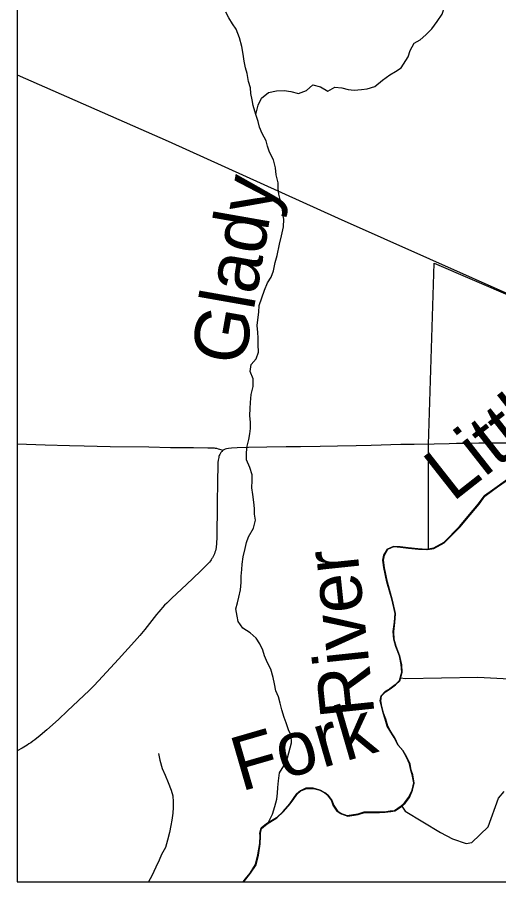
# Model space of a CAD drawing. Extents: x 0 to 1052, y -194 to 246.
# Drawn here: x 1.982 to 2.825, y 14.205 to 15.72 of the extents above; entities that cross this region are included whole.
import ezdxf

# ---------------------------------------------------------------- set-up
doc = ezdxf.new("R2010")
doc.units = 0
for name, color, linetype in [('GM_X_Corporation', 7, 'Continuous'), ('GM_X_County_Road', 7, 'Continuous'), ('GM_X_Major_River', 7, 'Continuous'), ('GM_X_Major_River_Text', 7, 'Continuous'), ('GM_X_Minor_River', 7, 'Continuous'), ('GM_X_Minor_River_Text', 7, 'Continuous'), ('GM_X_Rail_Line', 7, 'Continuous')]:
    doc.layers.add(name, color=color, linetype=linetype)

msp = doc.modelspace()

# ---------------------------------------------------------------- linework, layer by layer
at = {"layer": 'GM_X_Corporation'}
for points in [[(1.9822, 21.0055), (1.9822, 14.2055), (2.3779, 14.2055), (2.3814, 14.2102), (2.39, 14.2207), (2.3994, 14.2357), (2.4035, 14.2523), (2.4066, 14.2724), (2.4072, 14.2857), (2.4069, 14.2907), (2.409, 14.299), (2.4186, 14.3071), (2.4359, 14.3174), (2.4476, 14.3286), (2.4592, 14.3421), (2.4658, 14.3511), (2.4709, 14.3586), (2.4779, 14.3649), (2.4875, 14.3692), (2.5, 14.3694), (2.5121, 14.3661), (2.5207, 14.361), (2.526, 14.3571), (2.5323, 14.3482), (2.5355, 14.3394), (2.5425, 14.329), (2.5489, 14.3247), (2.5599, 14.3207), (2.5782, 14.3238), (2.5892, 14.327), (2.6029, 14.3271), (2.6158, 14.3272), (2.6253, 14.3274), (2.6352, 14.3288), (2.6425, 14.3298), (2.6525, 14.3364), (2.6602, 14.3435), (2.668, 14.3536), (2.6736, 14.366), (2.6765, 14.3785), (2.6737, 14.393), (2.6712, 14.401), (2.6691, 14.4117), (2.6637, 14.4239), (2.6571, 14.4351), (2.6485, 14.4451), (2.6423, 14.4578), (2.636, 14.4674), (2.6301, 14.4782), (2.6266, 14.4904), (2.6226, 14.5011), (2.6198, 14.513), (2.6177, 14.5225), (2.6194, 14.5312), (2.6264, 14.5387), (2.6344, 14.5434), (2.6437, 14.5505), (2.6514, 14.5579), (2.6555, 14.5727), (2.6546, 14.586), (2.6515, 14.6009), (2.645, 14.6177), (2.6414, 14.6303), (2.6406, 14.644), (2.6424, 14.6599), (2.6438, 14.6751), (2.6386, 14.6984), (2.6293, 14.7305), (2.6241, 14.7557), (2.6225, 14.769), (2.6242, 14.7777), (2.6304, 14.7882), (2.6408, 14.7929), (2.6525, 14.792), (2.6666, 14.7902), (2.6836, 14.7883), (2.6996, 14.7876), (2.711, 14.7897), (2.7291, 14.7996), (2.7566, 14.8275), (2.7741, 14.8485), (2.79, 14.8672), (2.7998, 14.881), (2.8225, 14.8973), (2.8433, 14.9121)], [(1.9822, 21.0055), (1.9822, 14.2055), (2.3779, 14.2055), (2.3814, 14.2102), (2.39, 14.2207), (2.3994, 14.2357), (2.4035, 14.2523), (2.4066, 14.2724), (2.4072, 14.2857), (2.4069, 14.2907), (2.409, 14.299), (2.4186, 14.3071), (2.4359, 14.3174), (2.4476, 14.3286), (2.4592, 14.3421), (2.4658, 14.3511), (2.4709, 14.3586), (2.4779, 14.3649), (2.4875, 14.3692), (2.5, 14.3694), (2.5121, 14.3661), (2.5207, 14.361), (2.526, 14.3571), (2.5323, 14.3482), (2.5355, 14.3394), (2.5425, 14.329), (2.5489, 14.3247), (2.5599, 14.3207), (2.5782, 14.3238), (2.5892, 14.327), (2.6029, 14.3271), (2.6158, 14.3272), (2.6253, 14.3274), (2.6352, 14.3288), (2.6425, 14.3298), (2.6525, 14.3364), (2.6602, 14.3435), (2.668, 14.3536), (2.6736, 14.366), (2.6765, 14.3785), (2.6737, 14.393), (2.6712, 14.401), (2.6691, 14.4117), (2.6637, 14.4239), (2.6571, 14.4351), (2.6485, 14.4451), (2.6423, 14.4578), (2.636, 14.4674), (2.6301, 14.4782), (2.6266, 14.4904), (2.6226, 14.5011), (2.6198, 14.513), (2.6177, 14.5225), (2.6194, 14.5312), (2.6264, 14.5387), (2.6344, 14.5434), (2.6437, 14.5505), (2.6514, 14.5579), (2.6555, 14.5727), (2.6546, 14.586), (2.6515, 14.6009), (2.645, 14.6177), (2.6414, 14.6303), (2.6406, 14.644), (2.6424, 14.6599), (2.6438, 14.6751), (2.6386, 14.6984), (2.6293, 14.7305), (2.6241, 14.7557), (2.6225, 14.769), (2.6242, 14.7777), (2.6304, 14.7882), (2.6408, 14.7929), (2.6525, 14.792), (2.6666, 14.7902), (2.6836, 14.7883), (2.6996, 14.7876), (2.711, 14.7897), (2.7291, 14.7996), (2.7566, 14.8275), (2.7741, 14.8485), (2.79, 14.8672), (2.7998, 14.881), (2.8225, 14.8973), (2.8433, 14.9121)], [(2.8341, 14.9056), (2.8001, 14.8813), (2.7871, 14.8635), (2.7571, 14.8282), (2.7291, 14.7996), (2.7108, 14.7896), (2.7022, 14.7881), (2.7023, 14.9715), (2.712, 15.289), (2.9863, 15.171)], [(2.8433, 14.9121), (2.8225, 14.8973), (2.7998, 14.881), (2.79, 14.8672), (2.7741, 14.8485), (2.7566, 14.8275), (2.7291, 14.7996), (2.711, 14.7897), (2.6996, 14.7876), (2.6836, 14.7883), (2.6666, 14.7902), (2.6525, 14.792), (2.6408, 14.7929), (2.6304, 14.7882), (2.6242, 14.7777), (2.6225, 14.769), (2.6241, 14.7557), (2.6293, 14.7305), (2.6386, 14.6984), (2.6438, 14.6751), (2.6424, 14.6599), (2.6406, 14.644), (2.6414, 14.6303), (2.645, 14.6177), (2.6515, 14.6009), (2.6546, 14.586), (2.6555, 14.5727), (2.6514, 14.5579), (2.6437, 14.5505), (2.6344, 14.5434), (2.6264, 14.5387), (2.6194, 14.5312), (2.6177, 14.5225), (2.6198, 14.513), (2.6226, 14.5011), (2.6266, 14.4904), (2.6301, 14.4782), (2.636, 14.4674), (2.6423, 14.4578), (2.6485, 14.4451), (2.6571, 14.4351), (2.6637, 14.4239), (2.6691, 14.4117), (2.6712, 14.401), (2.6737, 14.393), (2.6765, 14.3785), (2.6736, 14.366), (2.668, 14.3536), (2.6602, 14.3435), (2.6525, 14.3364), (2.6425, 14.3298), (2.6352, 14.3288), (2.6253, 14.3274), (2.6158, 14.3272), (2.6029, 14.3271), (2.5892, 14.327), (2.5782, 14.3238), (2.5599, 14.3207), (2.5489, 14.3247), (2.5425, 14.329), (2.5355, 14.3394), (2.5323, 14.3482), (2.526, 14.3571), (2.5207, 14.361), (2.5121, 14.3661), (2.5, 14.3694), (2.4875, 14.3692), (2.4779, 14.3649), (2.4709, 14.3586), (2.4658, 14.3511), (2.4592, 14.3421), (2.4476, 14.3286), (2.4359, 14.3174), (2.4186, 14.3071), (2.409, 14.299), (2.4069, 14.2907), (2.4072, 14.2857), (2.4066, 14.2724), (2.4035, 14.2523), (2.3994, 14.2357), (2.39, 14.2207), (2.3814, 14.2102), (2.3779, 14.2055), (8.7822, 14.2055)], [(2.8433, 14.9121), (2.8225, 14.8973), (2.7998, 14.881), (2.79, 14.8672), (2.7741, 14.8485), (2.7566, 14.8275), (2.7291, 14.7996), (2.711, 14.7897), (2.6996, 14.7876), (2.6836, 14.7883), (2.6666, 14.7902), (2.6525, 14.792), (2.6408, 14.7929), (2.6304, 14.7882), (2.6242, 14.7777), (2.6225, 14.769), (2.6241, 14.7557), (2.6293, 14.7305), (2.6386, 14.6984), (2.6438, 14.6751), (2.6424, 14.6599), (2.6406, 14.644), (2.6414, 14.6303), (2.645, 14.6177), (2.6515, 14.6009), (2.6546, 14.586), (2.6555, 14.5727), (2.6514, 14.5579), (2.6437, 14.5505), (2.6344, 14.5434), (2.6264, 14.5387), (2.6194, 14.5312), (2.6177, 14.5225), (2.6198, 14.513), (2.6226, 14.5011), (2.6266, 14.4904), (2.6301, 14.4782), (2.636, 14.4674), (2.6423, 14.4578), (2.6485, 14.4451), (2.6571, 14.4351), (2.6637, 14.4239), (2.6691, 14.4117), (2.6712, 14.401), (2.6737, 14.393), (2.6765, 14.3785), (2.6736, 14.366), (2.668, 14.3536), (2.6602, 14.3435), (2.6525, 14.3364), (2.6425, 14.3298), (2.6352, 14.3288), (2.6253, 14.3274), (2.6158, 14.3272), (2.6029, 14.3271), (2.5892, 14.327), (2.5782, 14.3238), (2.5599, 14.3207), (2.5489, 14.3247), (2.5425, 14.329), (2.5355, 14.3394), (2.5323, 14.3482), (2.526, 14.3571), (2.5207, 14.361), (2.5121, 14.3661), (2.5, 14.3694), (2.4875, 14.3692), (2.4779, 14.3649), (2.4709, 14.3586), (2.4658, 14.3511), (2.4592, 14.3421), (2.4476, 14.3286), (2.4359, 14.3174), (2.4186, 14.3071), (2.409, 14.299), (2.4069, 14.2907), (2.4072, 14.2857), (2.4066, 14.2724), (2.4035, 14.2523), (2.3994, 14.2357), (2.39, 14.2207), (2.3814, 14.2102), (2.3779, 14.2055), (5.0927, 14.2055)]]:
    msp.add_lwpolyline(points, dxfattribs=at)
at = {"layer": 'GM_X_County_Road'}
for points in [[(1.9822, 14.9723), (2.0308, 14.971), (2.0736, 14.9698), (2.0991, 14.9691), (2.145, 14.9681), (2.2127, 14.967), (2.2506, 14.9663), (2.2798, 14.9663), (2.291, 14.9661), (2.3158, 14.9656), (2.3205, 14.9655), (2.3251, 14.9654), (2.3269, 14.9653), (2.3289, 14.9651), (2.3311, 14.9648), (2.3342, 14.9639), (2.3427, 14.9613)], [(2.3427, 14.9613), (2.3417, 14.9607), (2.3401, 14.9592), (2.3387, 14.9573), (2.3373, 14.955), (2.3366, 14.9537), (2.3359, 14.9521), (2.3353, 14.9502), (2.3348, 14.9484), (2.3344, 14.9462), (2.334, 14.944), (2.3336, 14.9396), (2.3325, 14.9017), (2.3323, 14.8725), (2.3319, 14.8489), (2.3318, 14.8259), (2.3313, 14.8048), (2.3311, 14.8019), (2.331, 14.7992), (2.3308, 14.7962), (2.3305, 14.7931), (2.3302, 14.7907), (2.3297, 14.7882), (2.3291, 14.7853), (2.3283, 14.7827), (2.3275, 14.78), (2.3264, 14.7775), (2.3253, 14.775), (2.3241, 14.773), (2.3231, 14.7714), (2.3218, 14.7694), (2.3203, 14.7674), (2.3188, 14.7655), (2.3172, 14.7636), (2.3147, 14.7609), (2.3125, 14.7587), (2.3024, 14.7486), (2.2784, 14.7261), (2.2528, 14.702), (2.2476, 14.6971), (2.244, 14.6935), (2.2401, 14.6897), (2.2365, 14.6858), (2.2333, 14.6823), (2.2301, 14.6785), (2.2257, 14.6733), (2.2053, 14.6474), (2.1967, 14.6368), (2.1874, 14.626), (2.1595, 14.5952), (2.1245, 14.5573), (2.1159, 14.5484), (2.108, 14.5405), (2.0701, 14.5046), (2.0541, 14.4899), (2.0338, 14.4716), (2.0221, 14.4614), (2.0129, 14.4541), (2.0094, 14.4515), (2.0059, 14.449), (2.0024, 14.4467), (1.9992, 14.4446), (1.9907, 14.4396), (1.9822, 14.435)], [(2.7122, 14.972), (2.6774, 14.9716), (2.6537, 14.9712), (2.6016, 14.9695), (2.5755, 14.969), (2.5426, 14.9682), (2.5128, 14.9677), (2.4781, 14.9675), (2.4527, 14.9674), (2.4192, 14.9669), (2.3869, 14.9662), (2.367, 14.9656), (2.357, 14.9649), (2.3519, 14.9644), (2.3486, 14.9638), (2.346, 14.9631), (2.3439, 14.9621), (2.3427, 14.9613)], [(2.8378, 14.9737), (2.8204, 14.9736), (2.8011, 14.9737), (2.7905, 14.9735), (2.7675, 14.9731), (2.7514, 14.9729), (2.7383, 14.9726), (2.7122, 14.972)]]:
    msp.add_lwpolyline(points, dxfattribs=at)
at = {"layer": 'GM_X_Major_River'}
for points in [[(2.6611, 14.3431), (2.6689, 14.3532), (2.6744, 14.3656), (2.6773, 14.3781), (2.6746, 14.3926), (2.672, 14.4006), (2.67, 14.4113), (2.6645, 14.4236), (2.6579, 14.4347), (2.6493, 14.4448), (2.6431, 14.4574), (2.6369, 14.467), (2.631, 14.4778), (2.6274, 14.49), (2.6234, 14.5008), (2.6206, 14.5126), (2.6185, 14.5221), (2.6202, 14.5308), (2.6272, 14.5383), (2.6353, 14.5431), (2.6445, 14.5501), (2.6523, 14.5576), (2.6564, 14.5723), (2.6555, 14.5856), (2.6523, 14.6005), (2.6458, 14.6174), (2.6423, 14.63), (2.6414, 14.6437), (2.6432, 14.6596), (2.6447, 14.6747), (2.6394, 14.698), (2.6302, 14.7301), (2.6249, 14.7553), (2.6233, 14.7686), (2.625, 14.7773), (2.6313, 14.7879), (2.6416, 14.7926), (2.6534, 14.7916), (2.6674, 14.7898), (2.6845, 14.788), (2.7004, 14.7873), (2.7118, 14.7893), (2.7299, 14.7992), (2.7574, 14.8272), (2.7749, 14.8481), (2.7908, 14.8668), (2.8006, 14.8807), (2.8233, 14.897), (2.8441, 14.9117)], [(2.6611, 14.3431), (2.6689, 14.3532), (2.6744, 14.3656), (2.6773, 14.3781), (2.6746, 14.3926), (2.672, 14.4006), (2.67, 14.4113), (2.6645, 14.4236), (2.6579, 14.4347), (2.6493, 14.4448), (2.6431, 14.4574), (2.6369, 14.4671), (2.631, 14.4778), (2.6274, 14.49), (2.6234, 14.5008), (2.6206, 14.5126), (2.6185, 14.5221), (2.6202, 14.5308), (2.6272, 14.5383), (2.6353, 14.5431), (2.6445, 14.5501), (2.6523, 14.5576), (2.6564, 14.5723), (2.6555, 14.5856), (2.6523, 14.6005), (2.6458, 14.6174), (2.6423, 14.63), (2.6414, 14.6437), (2.6432, 14.6596), (2.6447, 14.6747), (2.6394, 14.698), (2.6302, 14.7301), (2.6249, 14.7553), (2.6233, 14.7686), (2.625, 14.7773), (2.6313, 14.7879), (2.6416, 14.7926), (2.6534, 14.7916), (2.6674, 14.7898), (2.6845, 14.788), (2.7004, 14.7873), (2.7118, 14.7893), (2.7299, 14.7992), (2.7574, 14.8272), (2.7749, 14.8481), (2.7908, 14.8668), (2.8006, 14.8807), (2.8233, 14.897), (2.8441, 14.9117)], [(2.379, 14.2055), (2.3823, 14.2099), (2.3908, 14.2203), (2.4002, 14.2353), (2.4044, 14.252), (2.4074, 14.2721), (2.408, 14.2854), (2.4078, 14.2903), (2.4098, 14.2986), (2.4195, 14.3068), (2.4368, 14.3171), (2.4484, 14.3283), (2.46, 14.3417), (2.4667, 14.3507), (2.4718, 14.3582), (2.4787, 14.3645), (2.4883, 14.3689), (2.5008, 14.369), (2.5129, 14.3658), (2.5216, 14.3606), (2.5268, 14.3567), (2.5331, 14.3479), (2.5364, 14.3391), (2.5434, 14.3287), (2.5498, 14.3244), (2.5607, 14.3204), (2.579, 14.3234), (2.5901, 14.3266), (2.6038, 14.3268), (2.6167, 14.3269), (2.6262, 14.3271), (2.6361, 14.3284), (2.6433, 14.3294), (2.6533, 14.336), (2.6611, 14.3431)], [(2.379, 14.2055), (2.3823, 14.2099), (2.3908, 14.2203), (2.4002, 14.2353), (2.4044, 14.252), (2.4074, 14.2721), (2.408, 14.2854), (2.4078, 14.2903), (2.4098, 14.2986), (2.4195, 14.3068), (2.4368, 14.3171), (2.4484, 14.3283), (2.46, 14.3417), (2.4667, 14.3507), (2.4718, 14.3582), (2.4787, 14.3645), (2.4883, 14.3689), (2.5008, 14.369), (2.5129, 14.3658), (2.5216, 14.3606), (2.5268, 14.3567), (2.5331, 14.3479), (2.5364, 14.3391), (2.5434, 14.3287), (2.5498, 14.3244), (2.5607, 14.3204), (2.579, 14.3234), (2.5901, 14.3266), (2.6038, 14.3268), (2.6167, 14.3269), (2.6262, 14.3271), (2.6361, 14.3284), (2.6433, 14.3294), (2.6533, 14.336), (2.6611, 14.3431)]]:
    msp.add_lwpolyline(points, dxfattribs=at)
at = {"layer": 'GM_X_Minor_River'}
for points in [[(2.6665, 15.6507), (2.6701, 15.6618), (2.6771, 15.6746), (2.6875, 15.6802), (2.6978, 15.6891), (2.7082, 15.6996), (2.7175, 15.7124), (2.726, 15.7252), (2.7304, 15.7381), (2.731, 15.7513), (2.7289, 15.7643), (2.7297, 15.7745), (2.7341, 15.7843), (2.7384, 15.7979), (2.7428, 15.8093), (2.7513, 15.824), (2.7587, 15.8394), (2.7654, 15.8538), (2.772, 15.8658), (2.7797, 15.876), (2.7882, 15.8861), (2.7987, 15.8989), (2.8098, 15.9098)], [(2.3779, 15.6549), (2.3754, 15.6686), (2.3711, 15.6839), (2.3652, 15.6988), (2.3589, 15.7083), (2.3526, 15.7187), (2.3474, 15.7286)], [(2.4112, 15.5161), (2.4064, 15.5275), (2.4038, 15.537), (2.3998, 15.5492), (2.3954, 15.5652), (2.3932, 15.5751), (2.3914, 15.5861), (2.3904, 15.5964), (2.3871, 15.6074), (2.3846, 15.6215), (2.3816, 15.631), (2.3795, 15.6428), (2.3779, 15.6549)], [(2.3998, 15.5492), (2.4037, 15.5659), (2.4096, 15.5783), (2.4222, 15.5881), (2.4359, 15.591), (2.4495, 15.5912), (2.4613, 15.5896), (2.4745, 15.586), (2.4883, 15.5912), (2.4998, 15.6017), (2.513, 15.5982), (2.5258, 15.5901), (2.5384, 15.5972), (2.5502, 15.5963), (2.5615, 15.5931), (2.5721, 15.5923), (2.5851, 15.5933), (2.5946, 15.5943), (2.6083, 15.5987), (2.6217, 15.6096), (2.6343, 15.619), (2.6446, 15.6246), (2.6541, 15.6313), (2.6665, 15.6507)], [(2.4214, 14.3088), (2.429, 14.3235), (2.4333, 14.3371), (2.4364, 14.35), (2.4381, 14.3603), (2.4382, 14.3705), (2.4394, 14.3823), (2.4415, 14.3963), (2.4488, 14.4087), (2.4554, 14.4227), (2.4621, 14.4485), (2.4615, 14.4614), (2.457, 14.4713), (2.453, 14.4839), (2.4493, 14.4934), (2.4453, 14.5067), (2.4427, 14.5185), (2.4394, 14.5295), (2.435, 14.5398), (2.4328, 14.552), (2.4303, 14.5634), (2.4263, 14.5779), (2.4203, 14.589), (2.4151, 14.6012), (2.4122, 14.6111), (2.4066, 14.6221), (2.4006, 14.6321), (2.3901, 14.6417), (2.3773, 14.6494), (2.369, 14.6612), (2.3669, 14.6707), (2.3651, 14.6833), (2.3675, 14.6939), (2.3699, 14.7037), (2.373, 14.7166), (2.3743, 14.7299), (2.3744, 14.7405), (2.3753, 14.7523), (2.3758, 14.7618), (2.3778, 14.7746), (2.381, 14.789), (2.3834, 14.7996), (2.3869, 14.8098), (2.3958, 14.8246), (2.3993, 14.8386), (2.3975, 14.8492), (2.3973, 14.8595), (2.3966, 14.8701), (2.3945, 14.8838), (2.3931, 14.8952), (2.3932, 14.9081), (2.3937, 14.9183), (2.3893, 14.9313), (2.3833, 14.9446), (2.3838, 14.9575), (2.3847, 14.9682), (2.3875, 14.9799), (2.3895, 14.9898), (2.3907, 14.9996), (2.3905, 15.0099), (2.3891, 15.0224), (2.3899, 15.0345), (2.3908, 15.0448), (2.3917, 15.0592), (2.3953, 15.0728), (2.395, 15.0865), (2.3898, 15.0991), (2.3919, 15.1116), (2.4003, 15.1214), (2.4046, 15.1331), (2.404, 15.1464), (2.4041, 15.1582), (2.4035, 15.1677), (2.4024, 15.1798), (2.4033, 15.1897), (2.405, 15.2029), (2.4058, 15.2151), (2.4102, 15.2283), (2.4148, 15.2416), (2.4203, 15.2544), (2.4265, 15.2646), (2.4308, 15.2756), (2.4339, 15.2903), (2.4371, 15.3025), (2.4415, 15.3225), (2.4447, 15.3369), (2.4482, 15.3525), (2.4488, 15.3661), (2.4473, 15.3756), (2.4463, 15.3851), (2.4437, 15.3958), (2.4401, 15.4099), (2.4391, 15.4201), (2.4388, 15.43), (2.4355, 15.4437), (2.4341, 15.4558), (2.4308, 15.4699), (2.4238, 15.4837), (2.4205, 15.4939), (2.4179, 15.5035), (2.4112, 15.5161)], [(2.6537, 14.5626), (2.6612, 14.5616), (2.7884, 14.5635), (2.8438, 14.561), (2.9689, 14.5554), (2.9793, 14.5446), (2.9921, 14.5383), (3.002, 14.5381), (3.0299, 14.5512), (3.0405, 14.5507)], [(2.2293, 14.4303), (2.2318, 14.4181), (2.2358, 14.404), (2.241, 14.3922), (2.2466, 14.3793), (2.2518, 14.3659), (2.2543, 14.3557), (2.255, 14.3454), (2.2553, 14.3355), (2.2544, 14.3257), (2.2528, 14.3135), (2.2511, 14.3041), (2.2487, 14.2916), (2.2452, 14.2783), (2.2416, 14.2654), (2.2347, 14.253), (2.2304, 14.2432), (2.225, 14.2311), (2.2176, 14.2159), (2.2122, 14.2055)], [(2.6554, 14.3379), (2.6616, 14.3293), (2.7232, 14.2914), (2.7442, 14.2804), (2.768, 14.2724), (2.7783, 14.2741), (2.8065, 14.3017), (2.8248, 14.3518), (2.8345, 14.3634)]]:
    msp.add_lwpolyline(points, dxfattribs=at)
at = {"layer": 'GM_X_Rail_Line'}
msp.add_lwpolyline([(1.9822, 15.6192), (2.2465, 15.5027), (2.5441, 15.3677), (3.0187, 15.1565)], dxfattribs=at)

# ---------------------------------------------------------------- texts
at = {"layer": 'GM_X_Major_River_Text'}
for s, rotation, p in [('Little', 38.1806, (2.7444, 14.8695)), ('River', 95.9969, (2.608, 14.4984)), ('Fork', 16.1809, (2.3739, 14.3632))]:
    msp.add_text(s, height=0.0947, rotation=rotation, dxfattribs=at).set_placement(p)
at = {"layer": 'GM_X_Minor_River_Text'}
msp.add_text('Glady', height=0.0947, rotation=79.9972, dxfattribs=at).set_placement((2.3788, 15.1073))

doc.saveas('drawing.dxf')
